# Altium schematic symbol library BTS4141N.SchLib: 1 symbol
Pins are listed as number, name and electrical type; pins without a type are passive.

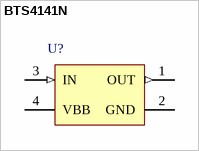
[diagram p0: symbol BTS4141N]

## BTS4141N
designator U?
Smart High-Side Power Switch, 1 Channel, 0.7 A Load Current, -40 to 150 degC, PG-SOT223 (SC-73), Reel, Green; Manufacturer: Infineon; PartNumber: BTS4141N; Channels: 1; Green: TRUE; Group: Automotive Qualified; Load Current (typ): 0.7 A; Ptot (max): 1.4 W; Recommended Operating Voltage Max.: 45 V; Recommended Operating Voltage Min.: 12 V; RON @ 25degreesC: 200 mOhm; RON(max) @ 150degreesC: 320 mOhm; toff (max): 150 us; ton (max): 100 us
footprint INF-PG-SOT223_SC-73_N (SOT223, 4-Leads, Body 6.5x3.5mm, Pitch 2.3mm, IPC Medium Density)
footprint INF-PG-SOT223_SC-73_L (SOT223, 4-Leads, Body 6.5x3.5mm, Pitch 2.3mm, IPC High Density)
footprint INF-PG-SOT223_SC-73_M (SOT223, 4-Leads, Body 6.5x3.5mm, Pitch 2.3mm, IPC Low Density)
pins: 1 OUT (out) "Output to the load", 2 GND (power) "Logic ground", 3 IN (in) "Input, activates the power switch in case of logic high signal", 4 VBB (power) "Positive power supply voltage"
